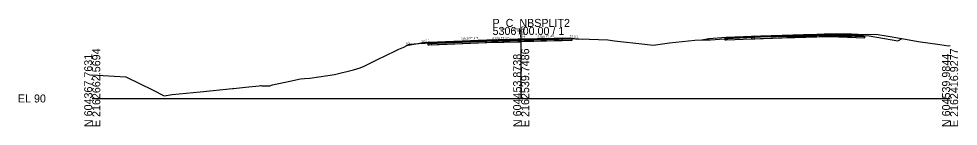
# Model space of a CAD drawing. Extents: x -26 to 1303, y -10 to 12038.
# Drawn here: x 974.3 to 1302.8, y 990.3 to 1027.8 of the extents above; entities that cross this region are included whole.
import ezdxf

# ---------------------------------------------------------------- set-up
doc = ezdxf.new("R2010")
doc.units = 0
for name, color, linetype in [('RD_GPK_XS_Cell', 7, 'Continuous'), ('RD_XS_Base', 7, 'Continuous'), ('RD_XS_ExGround', 7, 'Continuous'), ('RD_XS_ExPaveRet', 7, 'Continuous'), ('RD_XS_Greenside', 7, 'Continuous'), ('RD_XS_Pave', 7, 'Continuous'), ('RD_XS_PaveOvlay_CP', 7, 'Continuous'), ('RD_XS_TieSlope', 7, 'Continuous'), ('RD_XS_TX_Elev_EX', 7, 'Continuous'), ('RD_XS_TX_Elev_PR', 7, 'Continuous'), ('RD_XS_TX_ShdSlope', 7, 'Continuous'), ('RD_XS_TX_Slope', 7, 'Continuous')]:
    doc.layers.add(name, color=color, linetype=linetype)

msp = doc.modelspace()

# ---------------------------------------------------------------- linework, layer by layer
at = {"layer": 'RD_GPK_XS_Cell'}
for p, q in [((1150, 1000), (1150, 1025)), ((1000, 1000), (1150, 1000)), ((1150, 1000), (1300, 1000))]:
    msp.add_line(p, q, dxfattribs=at)
at = {"layer": 'RD_XS_Base'}
for p, q in [((1245, 1021.8), (1233.67, 1021.49)), ((1245.67, 1021.82), (1245, 1021.8)), ((1257.29, 1022.15), (1245.67, 1021.82)), ((1245.67, 1021.82), (1245.67, 1021.98)), ((1245.67, 1021.98), (1245.67, 1021.98)), ((1245.67, 1021.98), (1245.67, 1021.96)), ((1245.67, 1021.96), (1245.67, 1021.32)), ((1245.67, 1021.82), (1245.67, 1021.82)), ((1245.67, 1021.82), (1245.67, 1021.82)), ((1245.67, 1021.81), (1245.67, 1021.82)), ((1245.67, 1021.32), (1245.67, 1021.81)), ((1257.67, 1022.16), (1257.29, 1022.15)), ((1258.04, 1022.14), (1257.67, 1022.16)), ((1269.67, 1021.68), (1258.04, 1022.14)), ((1117.81, 1019.23), (1117.31, 1019.21)), ((1117.31, 1019.21), (1117.31, 1019.21)), ((1117.31, 1019.21), (1117.31, 1018.71)), ((1117.31, 1018.71), (1117.81, 1018.73)), ((1138, 1020.04), (1117.81, 1019.23)), ((1117.81, 1018.73), (1138, 1019.54)), ((1117.81, 1019.23), (1117.81, 1019.23)), ((1117.81, 1018.73), (1117.81, 1018.73)), ((1150, 1020.35), (1138, 1020.04)), ((1138, 1020.04), (1138, 1020.04)), ((1138, 1019.54), (1150, 1019.85)), ((1138, 1019.54), (1138, 1019.54)), ((1150, 1020.35), (1167.7, 1020.81)), ((1150, 1019.85), (1150, 1020.51)), ((1150, 1020.51), (1150, 1020.51)), ((1150, 1020.51), (1150, 1020.51)), ((1150, 1020.51), (1150, 1020.35)), ((1150, 1020.35), (1150, 1020.35)), ((1150, 1019.85), (1150, 1020.35)), ((1150, 1020.35), (1150, 1020.35)), ((1150, 1020.35), (1150, 1020.35)), ((1167.7, 1020.31), (1150, 1019.85)), ((1150, 1019.85), (1150, 1019.85)), ((1167.2, 1020.8), (1167.2, 1020.8)), ((1167.7, 1020.81), (1167.7, 1020.31)), ((1167.7, 1020.78), (1167.7, 1020.78)), ((1221.66, 1021), (1221.17, 1020.99)), ((1221.17, 1020.99), (1221.17, 1020.98)), ((1221.17, 1020.98), (1221.17, 1020.49)), ((1221.17, 1020.49), (1221.66, 1020.5)), ((1221.67, 1021.01), (1221.66, 1021)), ((1221.66, 1020.5), (1221.67, 1020.51)), ((1233.67, 1021.49), (1221.67, 1021.01)), ((1221.67, 1020.51), (1233.67, 1020.99)), ((1231.67, 1021.41), (1231.45, 1021.4)), ((1231.45, 1020.9), (1231.67, 1020.91)), ((1233.67, 1020.99), (1245, 1021.3)), ((1245, 1021.3), (1245.67, 1021.32)), ((1245.67, 1021.32), (1257.29, 1021.65)), ((1257.29, 1021.65), (1257.67, 1021.66)), ((1257.67, 1021.66), (1258.06, 1021.64)), ((1258.06, 1021.64), (1270.17, 1021.16)), ((1269.69, 1021.68), (1269.67, 1021.68)), ((1270.17, 1021.66), (1269.69, 1021.68)), ((1270.17, 1021.64), (1270.17, 1021.66)), ((1270.17, 1021.16), (1270.17, 1021.64))]:
    msp.add_line(p, q, dxfattribs=at)
at = {"layer": 'RD_XS_ExGround'}
msp.add_lwpolyline([(1000, 1008.22), (1007.61, 1007.85), (1011.79, 1007.52), (1021.28, 1002.85), (1025.15, 1000.93), (1027.89, 1001.34), (1037.78, 1002.37), (1049.09, 1003.46), (1049.35, 1003.5), (1049.41, 1003.5), (1053.64, 1003.95), (1058.37, 1004.45), (1058.79, 1004.49), (1058.92, 1004.48), (1059.27, 1004.47), (1062.1, 1004.47), (1062.98, 1004.71), (1069.06, 1005.99), (1072.77, 1006.82), (1074.27, 1006.95), (1076.11, 1007.15), (1082.34, 1008.07), (1084.77, 1008.41), (1091.41, 1010.06), (1093.74, 1010.65), (1095.13, 1011.27), (1100.92, 1014.2), (1101.51, 1014.48), (1107.23, 1017.22), (1108.92, 1017.93), (1110.84, 1018.93), (1114.23, 1019.22), (1118.69, 1019.44), (1135.03, 1020.2), (1139.6, 1020.4), (1141.25, 1020.43), (1143.56, 1020.5), (1145.76, 1020.55), (1147.84, 1020.6), (1148.3, 1020.6), (1148.87, 1020.69), (1150.99, 1020.76), (1152.06, 1020.76), (1161.53, 1020.95), (1164.3, 1021.03), (1168.98, 1020.83), (1173.78, 1020.71), (1180.3, 1020.5), (1182.63, 1020.19), (1193.21, 1018.97), (1196.17, 1018.65), (1201.87, 1019.4), (1210.78, 1020.35), (1214.5, 1020.46), (1216.23, 1020.5), (1220.96, 1020.87), (1226.1, 1021.27), (1230.52, 1021.6), (1237.92, 1021.87), (1245.77, 1022.15), (1248.77, 1022.24), (1254.27, 1022.39), (1261.83, 1022.5), (1265.5, 1022.52), (1267.74, 1022.49), (1274.69, 1022.41), (1277.68, 1021.92), (1283.1, 1020.96), (1288.81, 1019.96), (1296.44, 1018.84), (1299.5, 1018.45), (1300, 1018.5)], dxfattribs=at)
at = {"layer": 'RD_XS_ExPaveRet'}
for points in [[(1261.83, 1022.5), (1255.92, 1022.42), (1254.27, 1022.39), (1250.18, 1022.28), (1248.77, 1022.24), (1246.37, 1022.17), (1245.77, 1022.15), (1239.85, 1021.94), (1237.92, 1021.87), (1231.67, 1021.64), (1230.52, 1021.6), (1230.52, 1021.46), (1230.52, 1020.85), (1231.67, 1020.89), (1237.92, 1021.12), (1239.85, 1021.19), (1245.77, 1021.4), (1246.37, 1021.42), (1248.77, 1021.49), (1250.18, 1021.53), (1254.27, 1021.64), (1255.92, 1021.67), (1261.83, 1021.75), (1262.91, 1021.75), (1265.5, 1021.77), (1265.5, 1022.32), (1265.5, 1022.52), (1262.91, 1022.5), (1261.83, 1022.5)], [(1261.83, 1022.5), (1255.92, 1022.42), (1254.27, 1022.39), (1250.18, 1022.28), (1248.77, 1022.24), (1246.37, 1022.17), (1245.77, 1022.15), (1239.85, 1021.94), (1237.92, 1021.87), (1231.67, 1021.64), (1230.52, 1021.6), (1230.52, 1021.46), (1230.52, 1020.85), (1231.67, 1020.89), (1237.92, 1021.12), (1239.85, 1021.19), (1245.77, 1021.4), (1246.37, 1021.42), (1248.77, 1021.49), (1250.18, 1021.53), (1254.27, 1021.64), (1255.92, 1021.67), (1261.83, 1021.75), (1262.91, 1021.75), (1265.5, 1021.77), (1265.5, 1022.32), (1265.5, 1022.52), (1262.91, 1022.5), (1261.83, 1022.5)], [(1161.53, 1020.95), (1152.06, 1020.76), (1152.06, 1020.76), (1150.99, 1020.76), (1150.99, 1020.76), (1148.87, 1020.69), (1148.87, 1020.69), (1148.3, 1020.6), (1148.3, 1020.6), (1148.3, 1020.6), (1147.84, 1020.6), (1145.76, 1020.55), (1145.76, 1020.55), (1143.56, 1020.5), (1143.56, 1020.5), (1141.25, 1020.43), (1141.25, 1020.43), (1139.6, 1020.4), (1135.03, 1020.2), (1135.03, 1020.2), (1118.69, 1019.44), (1118.69, 1019.44), (1118.69, 1019.44), (1118.69, 1018.69), (1118.69, 1018.69), (1135.03, 1019.45), (1135.03, 1019.45), (1139.6, 1019.65), (1141.25, 1019.68), (1141.25, 1019.68), (1143.56, 1019.75), (1143.56, 1019.75), (1145.76, 1019.8), (1145.76, 1019.8), (1147.84, 1019.85), (1148.3, 1019.85), (1148.3, 1019.85), (1148.3, 1019.85), (1148.87, 1019.94), (1148.87, 1019.94), (1150.99, 1020.01), (1150.99, 1020.01), (1152.06, 1020.01), (1152.06, 1020.01), (1161.53, 1020.2), (1161.53, 1020.2), (1164.3, 1020.28), (1164.3, 1021.03), (1164.3, 1021.03), (1161.53, 1020.95), (1161.53, 1020.95)], [(1161.53, 1020.95), (1152.06, 1020.76), (1150.99, 1020.76), (1148.87, 1020.69), (1148.3, 1020.6), (1147.84, 1020.6), (1145.76, 1020.55), (1143.56, 1020.5), (1141.25, 1020.43), (1139.6, 1020.4), (1135.03, 1020.2), (1118.69, 1019.44), (1118.69, 1018.69), (1135.03, 1019.45), (1139.6, 1019.65), (1141.25, 1019.68), (1143.56, 1019.75), (1145.76, 1019.8), (1147.84, 1019.85), (1148.3, 1019.85), (1148.87, 1019.94), (1150.99, 1020.01), (1152.06, 1020.01), (1161.53, 1020.2), (1164.3, 1020.28), (1164.3, 1021.03), (1161.53, 1020.95)]]:
    msp.add_lwpolyline(points, dxfattribs=at)
at = {"layer": 'RD_XS_Greenside'}
for p, q in [((1271.67, 1021.84), (1281.67, 1020.17)), ((1115.81, 1019.39), (1109.8, 1018.39)), ((1215.67, 1020.84), (1213.13, 1020.42)), ((1281.67, 1020.17), (1283.2, 1020.94))]:
    msp.add_line(p, q, dxfattribs=at)
at = {"layer": 'RD_XS_Pave'}
for p, q in [((1233.67, 1021.8), (1221.67, 1021.32)), ((1245, 1022.12), (1233.67, 1021.8)), ((1245, 1021.96), (1233.67, 1021.64)), ((1233.67, 1021.64), (1245, 1021.96)), ((1233.67, 1021.49), (1245, 1021.8)), ((1245.67, 1022.14), (1245, 1022.12)), ((1245.67, 1021.98), (1245, 1021.96)), ((1245, 1021.96), (1245.67, 1021.98)), ((1245, 1021.8), (1245.67, 1021.82)), ((1257.29, 1022.47), (1245.67, 1022.14)), ((1257.29, 1022.31), (1245.67, 1021.98)), ((1245.67, 1021.98), (1257.29, 1022.31)), ((1245.67, 1021.82), (1257.29, 1022.15)), ((1245.67, 1021.82), (1245.67, 1021.98)), ((1245.67, 1021.98), (1245.67, 1021.98)), ((1245.67, 1021.98), (1245.67, 1021.98)), ((1245.67, 1021.98), (1245.67, 1021.98)), ((1245.67, 1021.98), (1245.67, 1021.98)), ((1245.67, 1021.98), (1245.67, 1021.82)), ((1245.67, 1021.82), (1245.67, 1021.82)), ((1245.67, 1021.82), (1245.67, 1021.82)), ((1257.67, 1022.48), (1257.29, 1022.47)), ((1257.67, 1022.32), (1257.29, 1022.31)), ((1257.29, 1022.31), (1257.67, 1022.32)), ((1257.29, 1022.15), (1257.67, 1022.16)), ((1258.04, 1022.46), (1257.67, 1022.48)), ((1258.04, 1022.3), (1257.67, 1022.32)), ((1257.67, 1022.32), (1258.04, 1022.3)), ((1257.67, 1022.16), (1258.04, 1022.14)), ((1269.67, 1022), (1258.04, 1022.46)), ((1269.67, 1021.84), (1258.04, 1022.3)), ((1258.04, 1022.3), (1269.67, 1021.84)), ((1258.04, 1022.14), (1269.67, 1021.68)), ((1269.67, 1021.99), (1269.67, 1022)), ((1269.67, 1021.84), (1269.67, 1021.99)), ((1269.67, 1021.83), (1269.67, 1021.84)), ((1269.67, 1021.68), (1269.67, 1021.83)), ((1138, 1020.36), (1117.81, 1019.55)), ((1117.81, 1019.39), (1138, 1020.2)), ((1138, 1020.2), (1117.81, 1019.39)), ((1117.81, 1019.23), (1138, 1020.04)), ((1117.81, 1019.55), (1117.81, 1019.55)), ((1117.81, 1019.55), (1117.81, 1019.39)), ((1117.81, 1019.39), (1117.81, 1019.39)), ((1117.81, 1019.39), (1117.81, 1019.23)), ((1150, 1020.67), (1138, 1020.36)), ((1138, 1020.2), (1150, 1020.51)), ((1150, 1020.51), (1138, 1020.2)), ((1138, 1020.36), (1138, 1020.36)), ((1138, 1020.04), (1150, 1020.35)), ((1138, 1020.2), (1138, 1020.2)), ((1138, 1020.2), (1138, 1020.2)), ((1138, 1020.04), (1138, 1020.04)), ((1167.2, 1021.12), (1150, 1020.67)), ((1167.2, 1020.96), (1150, 1020.51)), ((1150, 1020.51), (1167.2, 1020.96)), ((1150, 1020.35), (1167.2, 1020.8)), ((1150, 1020.67), (1150, 1020.67)), ((1150, 1020.51), (1150, 1020.51)), ((1150, 1020.51), (1150, 1020.51)), ((1150, 1020.51), (1150, 1020.35)), ((1150, 1020.51), (1150, 1020.51)), ((1150, 1020.35), (1150, 1020.51)), ((1150, 1020.51), (1150, 1020.51)), ((1150, 1020.51), (1150, 1020.51)), ((1150, 1020.35), (1150, 1020.35)), ((1150, 1020.35), (1150, 1020.35)), ((1167.2, 1020.96), (1167.2, 1021.12)), ((1167.2, 1021.12), (1167.2, 1021.12)), ((1167.2, 1020.8), (1167.2, 1020.96)), ((1167.2, 1020.96), (1167.2, 1020.96)), ((1233.67, 1021.64), (1221.67, 1021.16)), ((1221.67, 1021.16), (1233.67, 1021.64)), ((1221.67, 1021.01), (1233.67, 1021.49)), ((1221.67, 1021.32), (1221.67, 1021.32)), ((1221.67, 1021.32), (1221.67, 1021.16)), ((1221.67, 1021.16), (1221.67, 1021.16)), ((1221.67, 1021.16), (1221.67, 1021.01)), ((1231.67, 1021.72), (1231.45, 1021.71)), ((1231.67, 1021.56), (1231.45, 1021.56)), ((1231.45, 1021.56), (1231.67, 1021.56)), ((1231.45, 1021.4), (1231.67, 1021.41))]:
    msp.add_line(p, q, dxfattribs=at)
at = {"layer": 'RD_XS_PaveOvlay_CP'}
for p, q in [((1233.67, 1021.8), (1221.67, 1021.32)), ((1245, 1022.12), (1233.67, 1021.8)), ((1245.67, 1022.14), (1245, 1022.12)), ((1257.29, 1022.47), (1245.67, 1022.14)), ((1257.67, 1022.48), (1257.29, 1022.47)), ((1258.04, 1022.46), (1257.67, 1022.48)), ((1269.67, 1022), (1258.04, 1022.46)), ((1138, 1020.36), (1117.81, 1019.55)), ((1150, 1020.67), (1138, 1020.36)), ((1138, 1020.36), (1138, 1020.36)), ((1167.2, 1021.12), (1150, 1020.67)), ((1150, 1020.67), (1150, 1020.67)), ((1231.67, 1021.72), (1231.45, 1021.71))]:
    msp.add_line(p, q, dxfattribs=at)
at = {"layer": 'RD_XS_TieSlope'}
for p, q in [((1269.67, 1022), (1271.67, 1021.84)), ((1117.81, 1019.55), (1115.81, 1019.39)), ((1167.2, 1021.12), (1171.59, 1020.77)), ((1221.67, 1021.32), (1215.67, 1020.84))]:
    msp.add_line(p, q, dxfattribs=at)

# ---------------------------------------------------------------- texts
at = {"layer": 'RD_GPK_XS_Cell'}
for s, p in [('5306+00.00 / 1', (1140, 1022.2)), ('P_C_NBSPLIT2', (1140, 1025)), ('EL 90', (974, 998.6))]:
    msp.add_text(s, height=2.8, dxfattribs=at).set_placement(p)
for s, p in [('N 604367.7631', (1000, 990)), ('E 2162662.5694', (1002.8, 990)), ('N 604453.8738', (1150, 990)), ('E 2162539.7486', (1152.8, 990)), ('N 604539.9844', (1300, 990)), ('E 2162416.9277', (1302.8, 990))]:
    msp.add_text(s, height=2.8, rotation=90, dxfattribs=at).set_placement(p)
at = {"layer": 'RD_XS_TX_Elev_EX'}
msp.add_text('110.73', height=0.6, rotation=90, dxfattribs=at).set_placement((1149.7, 1021.47))
at = {"layer": 'RD_XS_TX_Elev_PR'}
msp.add_text('110.67', height=1, rotation=90, dxfattribs=at).set_placement((1151.3, 1021.15))
at = {"layer": 'RD_XS_TX_ShdSlope'}
for rotation, p in [(355.4261, (1166.98, 1021.44)), (4.5739, (1115.08, 1019.64))]:
    msp.add_text('12.5:1', height=0.75, rotation=rotation, dxfattribs=at).set_placement(p)
at = {"layer": 'RD_XS_TX_Slope'}
for s, rotation, p in [('0.028 FT./FT.', 1.6039, (1155.69, 1021.18)), ('6:1', 9.4642, (1109.7, 1018.87)), ('0.040 FT./FT.', 2.2906, (1128.99, 1020.47)), ('0.028 FT./FT.', 1.6039, (1139.97, 1020.59))]:
    msp.add_text(s, height=0.75, rotation=rotation, dxfattribs=at).set_placement(p)

doc.saveas('drawing.dxf')
